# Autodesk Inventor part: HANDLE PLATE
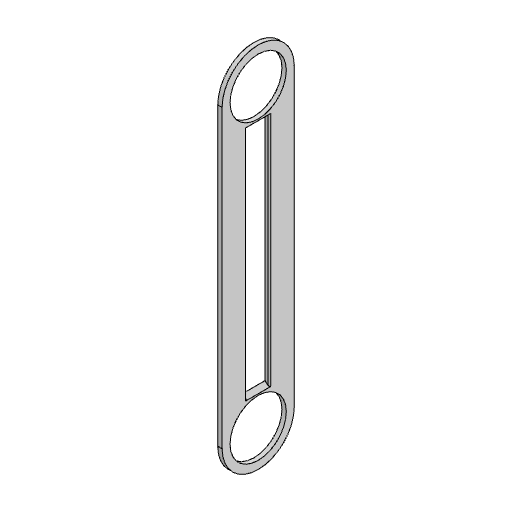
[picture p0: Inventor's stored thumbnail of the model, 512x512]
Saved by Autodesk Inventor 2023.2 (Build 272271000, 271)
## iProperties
Created: 2022-12
Part Number: HANDLE PLATE
Material: Generic
Document SubType Name: Modeling
Designer: AR
Mass: 21.8938 g
Surface Area: 180.294 cm^2
Volume: 21.8938 cm^3
Density: 1 g/cm^3
Appearance: Default
Author: AR
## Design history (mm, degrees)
derived "_2 SPOOL CORD WRAP MP.ipt"
feature "HANDLE PLATE::_2 SPOOL CORD WRAP MP.ipt" dims "d0" = 10
tag "TaggingFeature1"
node "HANDLE PLATE"
